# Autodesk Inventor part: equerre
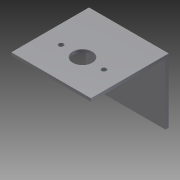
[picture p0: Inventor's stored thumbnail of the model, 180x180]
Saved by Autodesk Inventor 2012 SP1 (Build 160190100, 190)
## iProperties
Created: 2012-06
Part Number: equerre
Material: Default
Document SubType Name: Modeling
Designer: Bruno
Density: 1 g/cm^3
Author: Bruno
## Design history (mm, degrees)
sketch "Esquisse1"
  geometry: L1 (-13, -10.234)-(13, -10.234); L2 (13, -10.234)-(13, 18.309); L3 (13, 18.309)-(-13, 18.309); L4 (-13, 18.309)-(-13, -10.234); C1 r 3.175 at (0, 0) reference; C2 r 0.784 at (-7, 0) reference; C3 r 0.784 at (7, 0) reference; C4 r 1.05 at (7, 0); C5 r 1.05 at (-7, 0); 1 further point
  constraints: 8 end point, 2 centre point, 2 coincident, 2 parallel, 1 horizontal, 1 perpendicular
  dimensions: "d0" = 26 distance of L3.end L2.end; "d1" = 13 distance from line of L2 point (0, 0); "d10" = 2.1 diameter of C4; "d11" = 2.1 diameter of C5
extrude "Extrusion1" new body sketch "Esquisse1" distance "d2" = 1; taper "d3" = 0 deg
sketch "Esquisse2"
  geometry: L1 (13, 18.309)-(13, -10.234) reference; L2 (-13, 18.309)-(13, 18.309); L3 (13, 18.309)-(13, 17.262); L4 (13, 17.262)-(-13, 17.262); L5 (-13, 17.262)-(-13, 18.309)
  constraints: 8 end point, 2 parallel, 1 horizontal, 1 perpendicular, 1 point on line
extrude "Extrusion2" join sketch "Esquisse2" distance "d4" = 20; taper "d5" = 0 deg
sketch "Esquisse3"
  geometry: L1 (0, 0)-(26, 0) reference; L2 (26, 21)-(0, 21) reference; L3 (13, 21)-(13, 0); C1 r 2.1 at (13, 10.5); 2 further points
  constraints: 3 midpoint, 2 end point, 1 centre point, 1 coincident
  dimensions: "d6" = 4.2 diameter of C1
extrude "Extrusion3" cut sketch "Esquisse3" distance "d7" = 20; taper "d8" = 0 deg
fillet "Congé1" dims "d9" = 1
node "Solide1"
node "Référence1"
node "Référence2"
node "Référence3"
